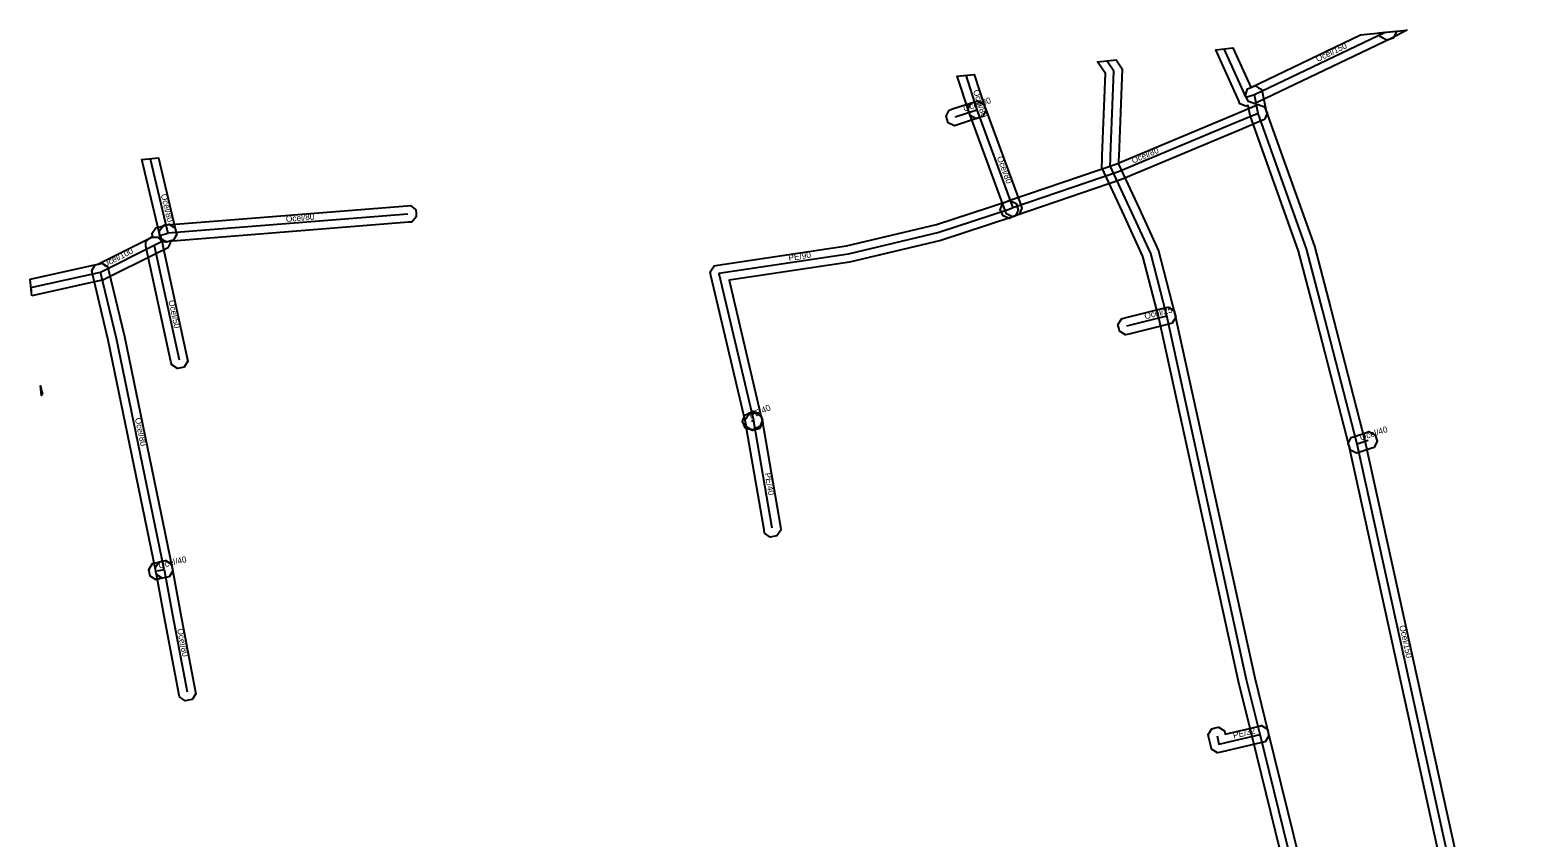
# Model space of a CAD drawing. Extents: x -697438 to -697243, y -1038718 to -1038521.
# Drawn here: x -697438.3 to -697256.2, y -1038618.2 to -1038520.6 of the extents above; entities that cross this region are included whole.
import ezdxf

# ---------------------------------------------------------------- set-up
doc = ezdxf.new("R2010")
doc.units = 0
for name, color, linetype in [('1', 7, 'Continuous'), ('14', 7, 'Continuous'), ('18', 7, 'Continuous'), ('20', 7, 'Continuous'), ('24', 7, 'Continuous'), ('30', 7, 'Continuous')]:
    doc.layers.add(name, color=color, linetype=linetype)

msp = doc.modelspace()

# ---------------------------------------------------------------- linework, layer by layer
at = {"layer": '1'}
for points in [[(-697290.87, -1038527.52), (-697277.61, -1038521.17), (-697272.03, -1038520.6), (-697273.91, -1038521.62), (-697290.01, -1038529.32), (-697290.38, -1038529.5), (-697291.16, -1038529.23), (-697291.34, -1038528.85), (-697291.52, -1038528.48), (-697291.25, -1038527.7)], [(-697275.35, -1038520.94), (-697273.31, -1038520.73), (-697273.29, -1038520.82), (-697273.67, -1038521.56), (-697274.06, -1038521.68), (-697274.46, -1038521.81), (-697275.19, -1038521.42), (-697275.32, -1038521.03)], [(-697324.89, -1038530.54), (-697326.32, -1038526.16), (-697324.28, -1038525.95), (-697322.99, -1038529.92), (-697322.86, -1038530.31), (-697323.24, -1038531.05), (-697323.63, -1038531.18), (-697324.03, -1038531.31), (-697324.77, -1038530.93)], [(-697327.28, -1038530.26), (-697326.88, -1038530.13), (-697324.25, -1038529.28), (-697323.86, -1038529.15), (-697323.12, -1038529.53), (-697322.99, -1038529.92), (-697322.86, -1038530.31), (-697323.24, -1038531.05), (-697323.63, -1038531.18), (-697326.27, -1038532.04), (-697326.66, -1038532.16), (-697327.4, -1038531.79), (-697327.53, -1038531.39), (-697327.65, -1038531)], [(-697323.15, -1038529.49), (-697323, -1038529.88), (-697318.65, -1038541.72), (-697318.51, -1038542.11), (-697318.85, -1038542.86), (-697319.24, -1038543.01), (-697319.63, -1038543.15), (-697320.38, -1038542.8), (-697320.53, -1038542.41), (-697324.88, -1038530.57), (-697325.02, -1038530.19), (-697324.68, -1038529.43), (-697324.29, -1038529.29), (-697323.9, -1038529.15)], [(-697289.22, -1038531.42), (-697289.6, -1038531.58), (-697292.24, -1038532.71), (-697306.47, -1038538.67), (-697319.22, -1038543), (-697319.63, -1038543.18), (-697320.01, -1038543.35), (-697320.79, -1038543.06), (-697320.95, -1038542.68), (-697321.12, -1038542.3), (-697320.83, -1038541.53), (-697320.45, -1038541.36), (-697319.95, -1038541.14), (-697307.18, -1038536.8), (-697293.02, -1038530.86), (-697290.38, -1038529.74), (-697290, -1038529.58), (-697289.23, -1038529.89), (-697289.07, -1038530.27), (-697288.91, -1038530.65)], [(-697422.89, -1038544.2), (-697424.77, -1038536.25), (-697422.76, -1038536.04), (-697420.95, -1038543.75), (-697420.67, -1038544.91), (-697420.58, -1038545.32), (-697421.01, -1038546.02), (-697421.42, -1038546.12), (-697421.82, -1038546.21), (-697422.52, -1038545.78), (-697422.62, -1038545.37)], [(-697392.18, -1038543.8), (-697392.59, -1038543.83), (-697421.57, -1038546.14), (-697421.98, -1038546.17), (-697422.61, -1038545.64), (-697422.64, -1038545.22), (-697422.67, -1038544.81), (-697422.14, -1038544.18), (-697421.72, -1038544.15), (-697392.75, -1038541.84), (-697392.34, -1038541.8), (-697391.71, -1038542.34), (-697391.67, -1038542.75), (-697391.64, -1038543.17)], [(-697319.33, -1038543.09), (-697319.73, -1038543.22), (-697328.28, -1038546.03), (-697339.31, -1038548.64), (-697353.87, -1038550.84), (-697349.95, -1038567.52), (-697349.91, -1038567.67), (-697349.81, -1038568.07), (-697350.24, -1038568.78), (-697350.64, -1038568.88), (-697351.04, -1038568.98), (-697351.75, -1038568.55), (-697351.85, -1038568.15), (-697351.89, -1038567.98), (-697356.06, -1038550.24), (-697356.16, -1038549.81), (-697355.92, -1038549.45), (-697355.67, -1038549.09), (-697355.24, -1038549.02), (-697339.69, -1038546.68), (-697328.82, -1038544.11), (-697320.35, -1038541.32), (-697319.96, -1038541.19), (-697319.22, -1038541.56), (-697319.09, -1038541.96), (-697318.96, -1038542.35)], [(-697438.07, -1038552.71), (-697438.27, -1038550.7), (-697430.11, -1038548.89), (-697423.73, -1038545.71), (-697423.47, -1038545.58), (-697423.48, -1038545.5), (-697423.53, -1038545.12), (-697423.11, -1038544.5), (-697422.75, -1038544.4), (-697421.9, -1038544.18), (-697421.5, -1038544.07), (-697420.79, -1038544.48), (-697420.68, -1038544.88), (-697420.57, -1038545.28), (-697420.98, -1038546), (-697421.39, -1038546.11), (-697421.39, -1038546.11), (-697421.36, -1038546.35), (-697421.66, -1038546.91), (-697421.94, -1038547.06), (-697422.84, -1038547.5), (-697429.43, -1038550.79)], [(-697422.29, -1038546.19), (-697422.29, -1038546.51), (-697419.32, -1038560.23), (-697419.23, -1038560.63), (-697419.68, -1038561.33), (-697420.08, -1038561.42), (-697420.49, -1038561.5), (-697421.18, -1038561.06), (-697421.27, -1038560.65), (-697424.29, -1038546.73), (-697424.29, -1038546.61), (-697424.29, -1038546.19), (-697423.7, -1038545.61), (-697423.29, -1038545.61), (-697422.87, -1038545.61)], [(-697423, -1038586.38), (-697423.08, -1038585.98), (-697428.83, -1038558.08), (-697430.74, -1038550.07), (-697430.84, -1038549.67), (-697430.41, -1038548.96), (-697430, -1038548.87), (-697429.6, -1038548.77), (-697428.89, -1038549.21), (-697428.8, -1038549.61), (-697426.88, -1038557.64), (-697421.12, -1038585.57), (-697421.04, -1038585.98), (-697421.5, -1038586.67), (-697421.9, -1038586.75), (-697422.31, -1038586.84)], [(-697438.12, -1038552.08), (-697438.13, -1038552.1), (-697438.14, -1038552)], [(-697306.49, -1038555.48), (-697306.09, -1038555.39), (-697301.24, -1038554.18), (-697300.84, -1038554.08), (-697300.13, -1038554.5), (-697300.03, -1038554.9), (-697299.93, -1038555.31), (-697300.35, -1038556.02), (-697300.76, -1038556.12), (-697305.61, -1038557.33), (-697306.01, -1038557.43), (-697306.72, -1038557), (-697306.82, -1038556.6), (-697306.92, -1038556.2)], [(-697436.79, -1038564.59), (-697436.9, -1038564.77), (-697437.01, -1038563.59), (-697436.88, -1038564.19)], [(-697351.97, -1038567.13), (-697351.59, -1038566.96), (-697351.4, -1038566.87), (-697351.36, -1038566.85), (-697350.99, -1038566.67), (-697350.2, -1038566.94), (-697350.02, -1038567.31), (-697349.84, -1038567.68), (-697350.11, -1038568.46), (-697350.48, -1038568.65), (-697350.55, -1038568.68), (-697350.77, -1038568.78), (-697351.14, -1038568.95), (-697351.92, -1038568.66), (-697352.09, -1038568.28), (-697352.26, -1038567.91)], [(-697349.58, -1038581.39), (-697349.65, -1038580.98), (-697351.87, -1038568.08), (-697351.94, -1038567.67), (-697351.46, -1038566.99), (-697351.05, -1038566.93), (-697350.64, -1038566.85), (-697349.96, -1038567.33), (-697349.89, -1038567.74), (-697347.68, -1038580.64), (-697347.61, -1038581.05), (-697348.09, -1038581.73), (-697348.5, -1038581.8), (-697348.9, -1038581.87)], [(-697275.98, -1038571.03), (-697276.38, -1038571.16), (-697277.71, -1038571.59), (-697278.1, -1038571.72), (-697278.84, -1038571.35), (-697278.97, -1038570.96), (-697279.1, -1038570.56), (-697278.73, -1038569.82), (-697278.33, -1038569.7), (-697277, -1038569.26), (-697276.61, -1038569.13), (-697275.87, -1038569.5), (-697275.74, -1038569.9), (-697275.61, -1038570.29)], [(-697423.51, -1038585.07), (-697423.11, -1038584.98), (-697422.33, -1038584.8), (-697421.93, -1038584.71), (-697421.22, -1038585.15), (-697421.13, -1038585.55), (-697421.04, -1038585.95), (-697421.48, -1038586.66), (-697421.88, -1038586.75), (-697422.66, -1038586.93), (-697423.06, -1038587.02), (-697423.76, -1038586.58), (-697423.86, -1038586.18), (-697423.95, -1038585.78)], [(-697421.2, -1038585.19), (-697421.12, -1038585.59), (-697420.11, -1038591.07), (-697418.33, -1038600.41), (-697418.26, -1038600.82), (-697418.72, -1038601.5), (-697419.13, -1038601.58), (-697419.54, -1038601.65), (-697420.22, -1038601.19), (-697420.3, -1038600.78), (-697422.08, -1038591.44), (-697423.09, -1038585.96), (-697423.16, -1038585.55), (-697422.69, -1038584.87), (-697422.29, -1038584.79), (-697421.88, -1038584.72)], [(-697294.06, -1038605.28), (-697293.97, -1038605.68), (-697289.98, -1038604.75), (-697289.57, -1038604.66), (-697288.87, -1038605.09), (-697288.78, -1038605.5), (-697288.68, -1038605.9), (-697289.12, -1038606.6), (-697289.52, -1038606.7), (-697294.49, -1038607.85), (-697294.89, -1038607.95), (-697295.6, -1038607.51), (-697295.69, -1038607.11), (-697295.92, -1038606.13), (-697296.01, -1038605.73), (-697295.57, -1038605.03), (-697295.17, -1038604.93), (-697294.77, -1038604.84)]]:
    msp.add_lwpolyline(points, close=True, dxfattribs=at)
for points in [[(-697267.51, -1038623.15), (-697278.99, -1038570.88), (-697283.19, -1038554.64), (-697285.11, -1038547.32), (-697290.96, -1038530.93), (-697291.2, -1038529.71), (-697291.48, -1038529.8), (-697292.18, -1038529.49), (-697292.33, -1038529.14), (-697295.11, -1038522.97), (-697293.02, -1038522.75), (-697290.87, -1038527.51), (-697290.74, -1038527.47), (-697290.32, -1038527.33), (-697289.93, -1038527.56), (-697289.55, -1038527.79), (-697289.46, -1038528.22), (-697289.02, -1038530.39), (-697283.19, -1038546.72), (-697281.25, -1038554.13), (-697277.05, -1038570.41), (-697265.56, -1038622.68)], [(-697279.38, -1038652.05), (-697290.72, -1038605.96), (-697292.35, -1038599.34), (-697301.97, -1038555.38), (-697303.89, -1038547.95), (-697306.14, -1038543.08), (-697308.87, -1038537.22), (-697308.83, -1038536.21), (-697308.81, -1038535.76), (-697308.42, -1038525.85), (-697309.4, -1038524.43), (-697307.13, -1038524.2), (-697306.39, -1038525.27), (-697306.81, -1038535.84), (-697306.83, -1038536.29), (-697306.85, -1038536.81), (-697304.32, -1038542.24), (-697302, -1038547.27), (-697300.03, -1038554.91), (-697290.4, -1038598.89), (-697288.78, -1038605.48), (-697277.36, -1038651.87)]]:
    msp.add_lwpolyline(points, dxfattribs=at)
at = {"layer": '14'}
for points in [[(-697274.66, -1038520.87), (-697290.44, -1038528.42)], [(-697256.21, -1038665.2), (-697257.05, -1038661.05), (-697260.06, -1038648.13), (-697266.53, -1038622.92), (-697278.02, -1038570.65), (-697282.22, -1038554.39), (-697284.15, -1038547.02), (-697289.99, -1038530.66), (-697290.44, -1038528.42), (-697291.42, -1038528.73), (-697294.07, -1038522.86)], [(-697325.3, -1038526.06), (-697323.94, -1038530.23)], [(-697326.58, -1038531.08), (-697323.94, -1038530.23)], [(-697323.94, -1038530.23), (-697319.59, -1038542.07)], [(-697289.99, -1038530.66), (-697292.63, -1038531.78), (-697306.83, -1038537.74), (-697319.59, -1038542.07), (-697320.04, -1038542.27)], [(-697423.77, -1038536.14), (-697421.92, -1038543.97), (-697421.64, -1038545.14)], [(-697392.67, -1038542.83), (-697421.64, -1038545.14)], [(-697320.04, -1038542.27), (-697328.55, -1038545.07), (-697339.5, -1038547.66), (-697355.09, -1038550.01), (-697350.92, -1038567.75), (-697350.88, -1038567.91)], [(-697438.17, -1038551.71), (-697429.77, -1038549.84), (-697423.29, -1038546.61), (-697422.39, -1038546.16), (-697422.49, -1038545.37), (-697421.64, -1038545.14)], [(-697423.29, -1038546.61), (-697423.29, -1038546.62), (-697420.29, -1038560.44)], [(-697422.1, -1038585.78), (-697427.86, -1038557.86), (-697429.77, -1038549.84)], [(-697351.18, -1038567.87), (-697350.98, -1038567.78), (-697350.92, -1038567.75)], [(-697348.67, -1038580.81), (-697350.88, -1038567.91)], [(-697276.69, -1038570.21), (-697278.02, -1038570.65)]]:
    msp.add_lwpolyline(points, dxfattribs=at)
at = {"layer": '18'}
for points in [[(-697422.88, -1038585.96), (-697422.1, -1038585.78)], [(-697422.1, -1038585.78), (-697421.09, -1038591.25), (-697419.32, -1038600.59)]]:
    msp.add_lwpolyline(points, dxfattribs=at)
at = {"layer": '24'}
for points in [[(-697266.11, -1038717.7), (-697266.3, -1038716.14), (-697267.01, -1038712.92), (-697276.58, -1038669.77), (-697276.93, -1038668.21), (-697278.78, -1038659.81), (-697278.85, -1038659.49), (-697278.37, -1038651.96), (-697289.75, -1038605.72), (-697291.38, -1038599.12), (-697301, -1038555.15), (-697302.95, -1038547.61), (-697305.23, -1038542.66), (-697307.86, -1038537.02), (-697307.83, -1038536.25), (-697307.81, -1038535.8), (-697307.41, -1038525.56), (-697308.26, -1038524.31)], [(-697305.85, -1038556.35), (-697301, -1038555.15)], [(-697294.94, -1038605.91), (-697294.72, -1038606.88), (-697289.75, -1038605.72)]]:
    msp.add_lwpolyline(points, dxfattribs=at)

# ---------------------------------------------------------------- texts
at = {"layer": '20'}
for s, rotation, p in [('Ocel/150', 25.5701, (-697282.8, -1038524.47)), ('Ocel/80', 17.9899, (-697325.46, -1038530.46)), ('Ocel/80', 288.0211, (-697324.42, -1038527.94)), ('Ocel/80', 290.1903, (-697321.55, -1038536)), ('Ocel/80', 22.7547, (-697305.09, -1038536.73)), ('Ocel/80', 283.2737, (-697422.49, -1038540.49)), ('Ocel/80', 4.5584, (-697407.36, -1038543.79)), ('Ocel/100', 26.5049, (-697429.34, -1038549.32)), ('PE/90', 8.5721, (-697346.64, -1038548.51)), ('Ocel/50', 282.2238, (-697421.59, -1038553.32)), ('PE/40', 24.3801, (-697351.25, -1038567.61)), ('Ocel/80', 281.6494, (-697425.62, -1038567.53)), ('Ocel/40', 18.1502, (-697277.56, -1038570.23)), ('PE/40', 279.743, (-697349.57, -1038574.16)), ('Ocel/40', 13.0107, (-697422.69, -1038585.67)), ('Ocel/80', 280.7758, (-697420.53, -1038592.99)), ('Ocel/150', 282.3955, (-697272.95, -1038592.62))]:
    msp.add_text(s, height=0.75, rotation=rotation, dxfattribs=at).set_placement(p)
at = {"layer": '30'}
for s, rotation, p in [('Ocel/25', 13.9918, (-697303.62, -1038555.55)), ('PE/32', 13.1125, (-697292.92, -1038606.22))]:
    msp.add_text(s, height=0.75, rotation=rotation, dxfattribs=at).set_placement(p)

doc.saveas('drawing.dxf')
